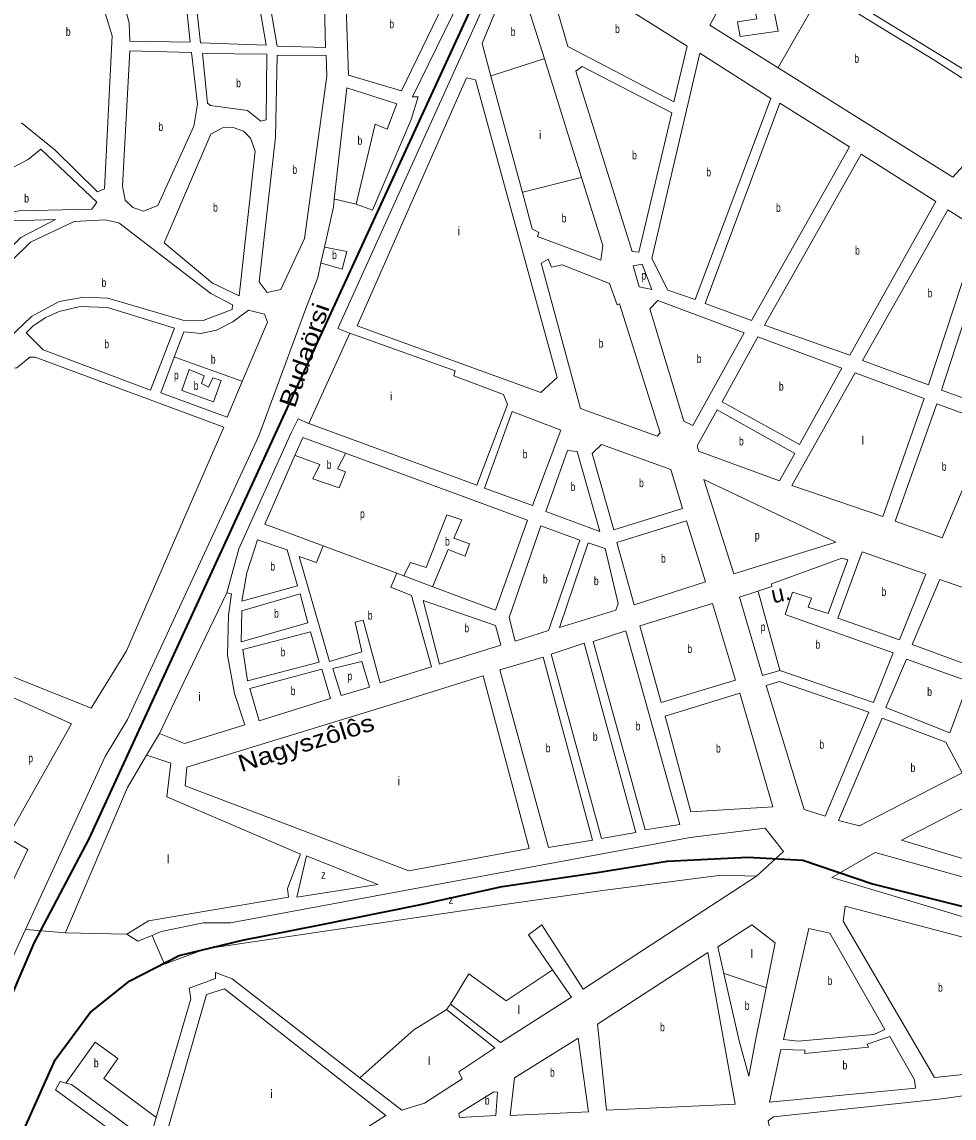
# Model space of a CAD drawing. Extents: x 639657 to 671642, y 222838 to 252123.
# Drawn here: x 648074 to 649169, y 236282 to 237569 of the extents above; entities that cross this region are included whole.
import ezdxf
from ezdxf.enums import TextEntityAlignment as Align

# ---------------------------------------------------------------- set-up
doc = ezdxf.new("R2010")
doc.units = 0
doc.header["$LTSCALE"] = 4
for name, color, linetype, lineweight in [('1', 7, 'Continuous', 13), ('21', 7, 'Continuous', 13), ('57', 7, 'Continuous', 35)]:
    doc.layers.add(name, color=color, linetype=linetype, lineweight=lineweight)
doc.layers.add('22', color=7, linetype='Continuous')
doc.layers.add('7', color=7, linetype='Continuous')

msp = doc.modelspace()

# ---------------------------------------------------------------- linework, layer by layer
at = {"layer": '1'}
for p, q in [((649167.54, 237387.09), (648962.215, 237515.472)), ((648485.97, 237348.354), (648466.758, 237355.344)), ((648264.4, 237205.4), (648253.167, 237175.527)), ((648359.66, 236979.18), (648394.815, 237060.136)), ((648428.159, 236953.689), (648359.66, 236979.18)), ((648937.039, 236565.79), (648733.55, 236432.94)), ((648733.55, 236432.94), (648684.736, 236508.716)), ((648935.92, 236372.66), (648948.453, 236434.804))]:
    msp.add_line(p, q, dxfattribs=at)
for points in [[(648254.02, 237981.68), (648247.99, 237983.13), (648181.41, 237912.62), (648180.29, 237896.05), (648248.49, 237711.3), (648266.09, 237648.23), (648277.25, 237605.11), (648283.86, 237544.73), (648361.03, 237542.22), (648330.04, 237723.02), (648273.61, 237889.81), (648264.29, 237942.2)], [(648109.77, 237833.46), (648158.88, 237887.89), (648171.57, 237886.07), (648239.72, 237707.77), (648266.1, 237602.64), (648271.82, 237545.48), (648200.89, 237546.76), (648200.25, 237568.48), (648173.08, 237666.3), (648172.5, 237681.13), (648107.94, 237822.47)], [(649014.45, 237615.58), (648948.94, 237656.48), (648951.26, 237661.02), (648939.15, 237669.29), (648980.29, 237746.67), (649048.84, 237703.64), (649137.09, 237644.67), (649176.39, 237625.03), (649293.79, 237530.85), (649238.75, 237467.54), (649191.95, 237506.25)], [(648430.69, 237539.21), (648373.94, 237541.05), (648357.75, 237636.39), (648416.42, 237657.36), (648429.03, 237620.49)], [(648453.41, 237633.19), (648457.87, 237506.77), (648519.94, 237488.42), (648581.24, 237614.8), (648557.49, 237626.19), (648523.01, 237635.34)], [(648839.83, 237475.46), (648715.2, 237540.34), (648690.28, 237627.42), (648703.08, 237637), (648855.52, 237540.77)], [(648192.24, 237376.57), (648201, 237535.58), (648273.44, 237533.46), (648280.48, 237472.66), (648276.01, 237447.03), (648233.72, 237353.73), (648217.24, 237347.12), (648204.52, 237351.31), (648195.63, 237359.83)], [(648292.08, 237473.84), (648286.35, 237532.29), (648362, 237531.48), (648361.03, 237454.48), (648354.82, 237452.92), (648339, 237465.46), (648295.76, 237471.08)], [(648432.52, 237505.68), (648431.64, 237529.76), (648374.04, 237530.3), (648372.19, 237434.15), (648353.01, 237263.86), (648362.37, 237251.47), (648378.24, 237254.84), (648406.02, 237314.89)], [(648870.43, 237532.52), (648813.91, 237291.35), (648832.75, 237254.32), (648864.87, 237243.43), (648953.9, 237479.32)], [(648798.79, 237298.74), (648790.83, 237299.52), (648724.93, 237511.61), (648732.19, 237516.84), (648837.59, 237462.54)], [(648702.88, 237151.82), (648683.5, 237134.01), (648467.84, 237212.45), (648596.29, 237503.54), (648607.06, 237501.27)], [(648876.53, 237238.38), (648931.09, 237218.67), (649046, 237422.53), (648964.27, 237473.82)], [(648348.28, 237417.58), (648329.53, 237247.73), (648298.23, 237262.28), (648241.25, 237309.71), (648296.08, 237437.53), (648309.98, 237444.76), (648322.44, 237445.3), (648334.52, 237441.11), (648342.55, 237432.8)], [(648036.14, 237341.36), (648020.91, 237334.13), (647956.16, 237294.38), (647947.36, 237300.59), (647944.97, 237309.18), (647952.04, 237320.37), (647969.9, 237343.02), (648024.18, 237377.81), (648081.48, 237407.59), (648096.62, 237419.99), (648162.34, 237357.8), (648156.41, 237349.36), (648070.9, 237347.27)], [(649046.46, 237177.8), (648946.4, 237213.22), (649060.05, 237413.84), (649147.41, 237358.52)], [(649061.35, 237171.48), (649138.77, 237142.95), (649198.67, 237325.01), (649161.48, 237348.54)], [(647978.05, 237242.85), (648008.9, 237203.08), (648017.07, 237204.62), (648052.92, 237295.92), (648073.14, 237316.11), (648113.76, 237337.35), (648063.71, 237335.59), (648028.35, 237324.94), (647999.79, 237310.36), (647962.25, 237285.99), (647960.34, 237278.26)], [(648027.41, 237201.92), (648028.42, 237185.59), (648036.22, 237179.21), (648048.39, 237188.14), (648085.65, 237223.32), (648117.93, 237240.82), (648147.1, 237246.04), (648175.05, 237245.01), (648263.41, 237218.94), (648287.05, 237218.73), (648321.31, 237231.52), (648321.68, 237237.12), (648295.98, 237250.21), (648188.15, 237333.3), (648172.21, 237337.03), (648135.49, 237334.75), (648084.15, 237310.62), (648061.8, 237288.48)], [(649154.3, 237136.86), (649385.27, 237053.18), (649450.68, 237199.6), (649265.5, 237280.69), (649219.43, 237311.23), (649214.73, 237308.6), (649210.42, 237309.86)], [(648823.64, 237086.48), (648776.17, 237238.09), (648773.39, 237236.99), (648764.34, 237262.07), (648708.89, 237283.92), (648696.02, 237281.44), (648692.28, 237290.65), (648683.95, 237286.06), (648730.1, 237115.3), (648820.46, 237082.8)], [(648792.064, 237282.711), (648802.618, 237284.823), (648814.228, 237254.955), (648799.301, 237258.274)], [(648862.03, 237095.23), (648922.42, 237204.18), (648821.26, 237242.17), (648811.69, 237232.19), (648851.45, 237100.29)], [(648079.39, 237204.12), (648099.35, 237184.31), (648225.32, 237136.87), (648253.4, 237209.39), (648174.73, 237233.82), (648142.7, 237235.03), (648118.04, 237229.21), (648102.21, 237221.97), (648087.48, 237212.15)], [(648608.49, 237025.14), (648644.52, 237120.1), (648639.9, 237131.67), (648581.66, 237153.5), (648582.89, 237159.53), (648459.54, 237203.55), (648411.37, 237097.51)], [(648987.31, 237072.73), (649037.37, 237162.44), (648938.58, 237199.59), (648896.57, 237122.86)], [(648978.33, 237024.69), (649085.49, 236988.47), (649133.99, 237126.99), (649052.68, 237156.99)], [(648981.83, 237062.35), (648963.88, 237030.14), (648868.98, 237065.18), (648867.42, 237071.19), (648890.64, 237113.56)], [(649211.64, 237097.6), (649148.88, 237120.68), (649099.94, 236982.8), (649154.93, 236963.31)], [(648617.33, 237021.78), (648650.19, 237111.76), (648707.14, 237089.71), (648674.05, 237001.44)], [(648726.3, 237064.72), (648752.79, 236970.77), (648689.38, 236994.27), (648714.89, 237065.91)], [(648769.53, 236972.65), (648850.09, 236997.69), (648836.53, 237043.38), (648755.01, 237072.95), (648744.15, 237062.52)], [(648910.33, 236920.811), (649030.2, 236957.987), (648875.091, 237031.614)], [(648729.68, 236960.66), (648683.53, 236977.44), (648646.54, 236869.79), (648653.48, 236841.89), (648692.68, 236854.51)], [(648876.93, 236911.49), (648854.95, 236983.33), (648772.9, 236957.84), (648793.17, 236884.69)], [(648397.76, 236907.06), (648332.61, 236888.82), (648338.3, 236922.21), (648351.03, 236960.82), (648385.96, 236949.1)], [(648759.43, 236950.83), (648739.16, 236957.53), (648705.75, 236857.86), (648771.74, 236878.26), (648774.46, 236886.24)], [(649060.96, 236946.95), (649032.5, 236869.05), (649104.96, 236843.27), (649136, 236920.77)], [(649192.3, 236811.17), (649221.62, 236889.94), (649152.18, 236914.46), (649119.62, 236837.81)], [(648410.01, 236863.3), (648331.57, 236841.28), (648332.72, 236877.64), (648400.86, 236897.62)], [(648636.76, 236837.22), (648630.52, 236860.39), (648545.56, 236889.71), (648564.56, 236815.05)], [(648912.44, 236796.11), (648824.81, 236769.71), (648799.86, 236860.02), (648885.13, 236885.97)], [(648423.35, 236817.18), (648339.11, 236795.33), (648333.59, 236832.05), (648413.33, 236852.79)], [(648806.07, 236620.28), (648745.24, 236841.45), (648783.59, 236853.85), (648846.84, 236626.68)], [(648755.02, 236610.13), (648695.75, 236826.58), (648734.52, 236839.42), (648795.36, 236616.96)], [(648439.524, 236809.779), (648473.56, 236818.103), (648482.427, 236787.792), (648449.175, 236778.181)], [(648692.81, 236599.45), (648635.54, 236808.39), (648686.54, 236823.27), (648744.3, 236608.1)], [(649113.13, 236820.77), (649088.76, 236763.76), (649164.04, 236734.35), (649186.45, 236794.34)], [(648436.66, 236774.51), (648352.9, 236748.14), (648341.99, 236786.11), (648426.66, 236808.82)], [(649068.82, 236758.42), (648964.03, 236794.65), (648948.18, 236789.78), (648992.8, 236643.95), (649017.58, 236636.22)], [(647984.42, 236666.97), (648050.57, 236781.68), (648132.45, 236744.6), (648062.74, 236620.94)], [(648860.02, 236641.43), (648829.69, 236753.84), (648917.32, 236780.67), (648956.02, 236647.26)], [(649033.32, 236631.2), (649084.58, 236751.25), (649159.21, 236723.12), (649178.47, 236687.39), (649058.09, 236624.98)], [(649107.25, 236608.23), (649251.37, 236682.68), (649266.1, 236560.45)], [(648408.59, 236589.672), (648397.311, 236541.151), (648492.414, 236555.876)], [(649145.87, 236329.44), (649187.52, 236333.48), (649226.9, 236481.59), (649041.18, 236530.63), (649038.56, 236512.75)], [(649087.73, 236385.68), (649074.89, 236379.96), (648985.78, 236372.04), (648968.58, 236373.82), (648998.25, 236504.21), (649023.01, 236498.84)], [(648879.68, 236476.01), (648750.28, 236391.8), (648760.94, 236291.04), (648911.72, 236298.02)], [(648238.56, 236243.84), (648331.62, 236176.53), (648501.84, 236284.56), (648312.35, 236433.56), (648291.14, 236426.91)], [(648647.75, 236284.83), (648652.9, 236328.96), (648727.66, 236375.68), (648739.47, 236288.9)], [(649123.64, 236316.76), (649122.69, 236326.43), (649093.4, 236377.34), (649067.05, 236368.28), (649068.37, 236364.85), (648993.66, 236357.28), (648993.62, 236361.58), (648965.47, 236362.18), (648952.1, 236300.12)], [(649211.77, 236051.33), (649200.52, 236190.58), (649195.28, 236199.35), (649206.93, 236216.23), (649295.793, 236324.572), (649154.49, 236304.35), (648956.78, 236283.17), (648950.81, 236278.38), (649005.5, 236003.83)], [(648630.99, 236284.67), (648632.66, 236312), (648628.35, 236312.61), (648587.34, 236287.07), (648588.25, 236282.34)]]:
    msp.add_lwpolyline(points, close=True, dxfattribs=at)
for points in [[(648003.985, 237761.114), (648010.17, 237755.54), (648061.18, 237682.04), (648081.36, 237661.79), (648105.57, 237647.18), (648136.37, 237639.93), (648159.34, 237620.79), (648180.42, 237553.03), (648171.43, 237373.15), (648163.08, 237369.85), (648113.39, 237418.64), (648073.97, 237450.75)], [(648635.931, 237692.189), (648533.101, 237481.453), (648539.735, 237481.453), (648531.442, 237454.904), (648485.97, 237348.354)], [(648652.517, 237667.299), (648445.197, 237209.322), (648459.04, 237203.751), (648459.54, 237203.55)], [(648962.215, 237515.472), (648882.14, 237565.54), (648930.9, 237655.67), (649013.526, 237605.308)], [(648624.978, 237505.815), (648614.59, 237544.14), (648646.29, 237620.56), (648658.77, 237618.96), (648687.863, 237526.037), (648731.544, 237386.519)], [(649013.526, 237605.308), (649145.35, 237524.96), (649197.26, 237491.03), (649233.24, 237459.1), (649167.54, 237387.09)], [(648673.67, 237326.18), (648662.028, 237369.131), (648624.978, 237505.815)], [(648441.134, 237361.26), (648455.86, 237491.91), (648514.717, 237473.117)], [(648514.717, 237473.117), (648503.247, 237443.289), (648489.15, 237449.097), (648466.758, 237355.344)], [(648731.544, 237386.519), (648756.59, 237306.52), (648753.97, 237289.5), (648679.77, 237317.42), (648681.23, 237322.16), (648673.67, 237326.18)], [(648429.601, 237304.644), (648440.04, 237351.55), (648441.134, 237361.26)], [(648407.68, 237232.75), (648421.72, 237269.23), (648425.5, 237286.215), (648429.601, 237304.644)], [(648407.68, 237232.75), (648352.317, 237083.212), (648198.071, 236749.685), (648171.93, 236706.47)], [(648333.109, 237147.029), (648362.71, 237216.64), (648358.97, 237225.85), (648340.44, 237230.84), (648321.88, 237217.12), (648302.64, 237207.05), (648284.41, 237203.22), (648264.4, 237205.4)], [(647887.225, 237144.175), (647891.754, 237141.496), (647972.84, 237093.53), (647981.22, 237091.19), (647995.9, 237093.86), (648035.57, 237158.12), (648045.83, 237163.38), (648057.02, 237162.19), (648068.19, 237163.16), (648083.75, 237175.34), (648089.77, 237175.4), (648311.48, 237093.36), (648197.15, 236830.36), (648155.48, 236763.09), (648040.74, 236809.02)], [(648253.167, 237175.527), (648237.38, 237133.54), (648315.24, 237105.01), (648333.109, 237147.029)], [(648314.89, 236898.76), (648329.098, 236950.465), (648390.464, 237086.531), (648398.757, 237103.124), (648410.87, 237097.733), (648411.37, 237097.51)], [(648394.815, 237060.136), (648404.01, 237081.31), (648454.443, 237062.768)], [(648454.443, 237062.768), (648668.2, 236984.18), (648630.34, 236878.45), (648556.784, 236905.822), (648522.641, 236918.528), (648514.394, 236921.597)], [(648428.159, 236953.689), (648420.356, 236934.171), (648399.79, 236941.27), (648435.37, 236818.15), (648473.3, 236829.26), (648465.66, 236864.03), (648474.87, 236866.69), (648495.15, 236793.11), (648555.35, 236811.74)], [(648964.533, 236807.337), (649074.3, 236769.65), (649097.37, 236828.36), (648970.57, 236873.21), (648979.12, 236899.31), (649001.54, 236892.21), (648997.56, 236881.85), (649021.27, 236874.54), (649044.29, 236937.55), (649037.18, 236939.42), (648954.53, 236909.41)], [(648555.35, 236811.74), (648531.75, 236895.61), (648507.551, 236905.338), (648514.394, 236921.597)], [(648954.53, 236909.41), (648954.99, 236905.97), (648938.586, 236900.555)], [(648314.89, 236898.76), (648320.49, 236897.52), (648316.87, 236872.33), (648315.61, 236825.43), (648324, 236780.35), (648335.96, 236743.68), (648265.05, 236721.74), (648235.71, 236733.51)], [(648938.586, 236900.555), (648916.982, 236893.423), (648944.154, 236801.674), (648964.533, 236807.337)], [(648518.57, 236770.53), (648616.05, 236801.11), (648670.04, 236598.16), (648570.94, 236580.04)], [(648265.96, 236672.06), (648268.11, 236693.81), (648518.57, 236770.53)], [(647872.536, 236168.951), (648000.85, 236383.75), (648056.41, 236455.5), (648078.362, 236503.191), (648171.93, 236706.47)], [(648220.619, 236708.06), (648221.119, 236707.893), (648248.996, 236698.597), (648244.467, 236658.952), (648401.49, 236591.6), (648385.98, 236551.45), (648387.15, 236541.14), (648223.03, 236513.17), (648197.61, 236497.66)], [(648570.94, 236580.04), (648528.47, 236571.91), (648265.96, 236672.06)], [(648060.306, 236553.799), (648081.03, 236597.02), (648037.15, 236623.07), (648016.29, 236580.08), (648009.14, 236586.89)], [(648227.067, 236496.276), (648237.98, 236500.83), (648287.52, 236510.97), (648319.11, 236510.83), (648859.02, 236611.1), (648947.02, 236622.02), (648968.78, 236594.91), (648937.039, 236565.79)], [(649076.172, 236593.467), (649025.49, 236564.273), (649393.627, 236453.931)], [(649405.677, 236499.881), (649269.685, 236539.688), (649076.172, 236593.467)], [(648684.736, 236508.716), (648669.371, 236496.734), (648697.553, 236455.736)], [(648948.453, 236434.804), (648959.08, 236487.5), (648931.59, 236508.54), (648891.44, 236482.79), (648898.586, 236451.434)], [(648197.61, 236497.66), (648210.59, 236489.4), (648227.067, 236496.276)], [(648471.177, 236328.982), (648321.26, 236445.26), (648301.63, 236452.6), (648301.7, 236445.72), (648270.65, 236434.25), (648272.71, 236421.58), (648231.905, 236282.345)], [(648697.553, 236455.736), (648719.67, 236423.56), (648636.17, 236370.32), (648577.7, 236415.58), (648573.04, 236409.09)], [(648898.586, 236451.434), (648916.58, 236372.48), (648927.822, 236330.656), (648935.92, 236372.66)], [(648573.04, 236409.09), (648629.78, 236364.02), (648587.29, 236335.88), (648591.46, 236327.54), (648547.25, 236299.17), (648520.47, 236290.75), (648471.177, 236328.982)], [(648125.935, 236322.695), (648119.36, 236324.46), (648113.87, 236314.73), (648219.07, 236237.64), (648171.68, 236073.32), (648139.86, 236052.6), (648140.01, 236037.11), (648097.67, 236007.21), (648072.36, 235735.76), (648060.22, 235639.98), (648068.62, 235637.88), (648076.25, 235693.63), (648105.08, 235690.13), (648075.64, 235537.49), (648070.11, 235527.13), (648098.499, 235356.253)], [(648231.905, 236282.345), (648225.5, 236260.49), (648217.57, 236258.48), (648132.51, 236320.93), (648125.935, 236322.695)]]:
    msp.add_lwpolyline(points, dxfattribs=at)
at = {"layer": '21'}
msp.add_line((648514.394, 236921.597), (648428.159, 236953.689), dxfattribs=at)
for points in [[(648917.866, 237552.321), (648962.268, 237558.324), (648952.078, 237608.163), (648969.061, 237611.561), (648965.664, 237627.419), (648928.303, 237619.49), (648937.36, 237573.049), (648914.716, 237569.651)], [(648270.811, 237161.004), (648261.926, 237136.31), (648299.244, 237123.035), (648308.366, 237147.925), (648298.414, 237151.244), (648293.439, 237140.458), (648285.146, 237144.606), (648288.463, 237153.733)]]:
    msp.add_lwpolyline(points, close=True, dxfattribs=at)
for points in [[(648962.215, 237515.472), (648962.501, 237515.972), (649013.24, 237604.808), (649013.526, 237605.308)], [(648624.978, 237505.815), (648625.478, 237505.976), (648687.363, 237525.876), (648687.863, 237526.037)], [(648662.028, 237369.131), (648662.528, 237369.256), (648731.044, 237386.394), (648731.544, 237386.519)], [(648466.758, 237355.344), (648441.634, 237361.145), (648441.134, 237361.26)], [(648429.601, 237304.644), (648430.101, 237304.551), (648455.979, 237299.757), (648450.174, 237279.015), (648426, 237286.069), (648425.5, 237286.215)], [(648253.167, 237175.527), (648253.667, 237175.349), (648332.609, 237147.207), (648333.109, 237147.029)], [(648394.815, 237060.136), (648395.315, 237059.954), (648424.051, 237049.499), (648415.922, 237032.496), (648446.958, 237022.146), (648454.347, 237040.628), (648444.741, 237044.324), (648454.18, 237062.268), (648454.443, 237062.768)], [(648556.784, 236905.822), (648556.989, 236906.323), (648574.795, 236949.696), (648594.746, 236941.564), (648599.919, 236956.349), (648581.445, 236963.003), (648591.051, 236984.442), (648573.317, 236990.356), (648548.932, 236928.256), (648530.458, 236934.171), (648522.891, 236919.029), (648522.641, 236918.528)], [(648314.89, 236898.76), (648264.414, 236793.658), (648235.71, 236733.51)], [(648964.533, 236807.337), (648964.394, 236807.837), (648938.725, 236900.055), (648938.586, 236900.555)], [(648198.071, 236670.037), (648220.619, 236708.06), (648235.71, 236733.51)], [(648198.071, 236670.037), (648125.308, 236499.625), (648125.095, 236499.125)], [(648937.039, 236565.79), (648895.56, 236566.92), (648753.26, 236548.39), (648638.24, 236532.28)], [(648227.067, 236496.276), (648229.209, 236491.276), (648241.533, 236462.506), (648290.303, 236480.249), (648638.24, 236532.28)], [(648125.095, 236499.125), (648078.862, 236503.147), (648078.362, 236503.191)], [(648197.61, 236497.66), (648197.11, 236497.67), (648125.095, 236499.125)], [(648697.553, 236455.736), (648697.053, 236455.403), (648643.082, 236419.405), (648599.276, 236451.18), (648578.003, 236416.08), (648577.7, 236415.58)], [(648948.453, 236434.804), (648947.953, 236434.971), (648899.086, 236451.267), (648898.586, 236451.434)], [(648573.04, 236409.09), (648572.54, 236408.782), (648534.662, 236385.44), (648471.677, 236329.427), (648471.177, 236328.982)], [(648125.935, 236322.695), (648126.291, 236323.195), (648160.25, 236370.834), (648186.852, 236351.613), (648170.595, 236327.956), (648231.405, 236282.717), (648231.905, 236282.345)]]:
    msp.add_lwpolyline(points, dxfattribs=at)
at = {"layer": '57'}
for points in [[(648764.444, 238156.794), (648760.356, 238056.15), (648755.321, 237936.134), (648642.478, 237674.613), (648152.957, 236609.517), (648088.384, 236487.179), (648047.188, 236392.076), (648029.423, 236322.423), (648014.054, 235904.557)], [(648056.694, 236178.651), (648077.383, 236269.56), (648113.411, 236350.225), (648154.274, 236405.789), (648201.05, 236442.66), (648258.986, 236472.731), (648333.334, 236490.803), (648424.501, 236508.623), (648540.719, 236532.049), (648638.396, 236553.637), (648749.723, 236570.284), (648832.114, 236583.501), (648926.736, 236588.164), (648991.288, 236584.772), (649073.136, 236556.912), (649237.676, 236515.501)]]:
    msp.add_lwpolyline(points, dxfattribs=at)

# ---------------------------------------------------------------- texts
at = {"layer": '22', "width": 1.2}
for s, rotation, p in [('Budaörsi', 71.005, (648415.346, 237174.561)), ('Nagyszôlôs', 17.55, (648410.957, 236712.908))]:
    msp.add_text(s, height=20, rotation=rotation, dxfattribs=at).set_placement(p, align=Align.CENTER)
at = {"layer": '22'}
msp.add_text('u.  ', height=20, rotation=12.4, dxfattribs=at).set_placement((648974.608, 236890.184), align=Align.CENTER)
at = {"layer": '7'}
for s, width, p in [('b', 0.75, (648125.881, 237552.987)), ('b', 0.75, (648505.749, 237561.88)), ('b', 0.75, (648770.841, 237556.23)), ('b', 0.75, (648648.371, 237552.806)), ('b', 0.75, (649051.797, 237521.38)), ('b', 0.75, (648325.875, 237492.605)), ('b', 0.75, (648234.622, 237441.35)), ('b', 0.75, (648468.418, 237425.036)), ('b', 0.75, (648790.905, 237407.79)), ('b', 0.75, (648391.946, 237390.885)), ('b', 0.75, (648877.99, 237387.975)), ('b', 0.75, (648076.954, 237357.185)), ('b', 0.75, (648298.736, 237346.515)), ('b', 0.75, (648959.864, 237346.245)), ('b', 0.75, (648708.08, 237333.773)), ('b', 0.75, (649052.789, 237295.82)), ('b', 0.75, (648438.564, 237290.631)), ('b', 0.75, (648167.726, 237258.12)), ('p', 0.75, (648801.789, 237266.57)), ('b', 0.75, (649137.969, 237245.745)), ('b', 0.75, (648171.011, 237185.95)), ('b', 0.75, (648751.525, 237186.725)), ('b', 0.75, (648296.152, 237167.925)), ('b', 0.75, (648866.791, 237168.7)), ('p', 0.75, (648252.804, 237149.584)), ('b', 0.75, (648276.024, 237137.139)), ('b', 0.75, (648963.279, 237136.16)), ('b', 0.75, (648916.347, 237071.85)), ('b', 0.75, (648662.387, 237056.6)), ('b', 0.75, (648432.179, 237044.324)), ('b', 0.75, (649154.555, 237041.995)), ('b', 0.75, (648718.664, 237018.34)), ('b', 0.75, (648799.003, 237022.8)), ('p', 0.75, (648471.343, 236986.66)), ('b', 0.75, (648571.1, 236954.131)), ('p', 0.75, (648935.097, 236961.386)), ('b', 0.75, (648365.968, 236924.82)), ('b', 0.75, (648824.772, 236934.01)), ('b', 0.75, (648686.073, 236909.665)), ('b', 0.75, (648745.961, 236907.695)), ('b', 0.75, (649083.872, 236895.11)), ('b', 0.75, (648370.416, 236869.45)), ('b', 0.75, (648480.473, 236867.19)), ('b', 0.75, (648593.869, 236852.38)), ('p', 0.75, (648941.89, 236853.778)), ('b', 0.75, (649006.192, 236833.014)), ('b', 0.75, (648378.103, 236824.06)), ('b', 0.75, (648855.774, 236827.84)), ('p', 0.75, (648456.564, 236795.924)), ('b', 0.75, (648389.843, 236778.48)), ('b', 0.75, (649137.42, 236777.56)), ('b', 0.75, (648795.028, 236737.065)), ('b', 0.75, (648744.75, 236724.775)), ('b', 0.75, (648689.358, 236711.36)), ('b', 0.75, (648889.376, 236711.05)), ('b', 0.75, (649010.862, 236715.435)), ('p', 0.75, (648081.734, 236699.491)), ('b', 0.75, (649117.851, 236688.115)), ('z', 0.8, (648425.616, 236562.672)), ('z', 0.8, (648575.534, 236533.477)), ('b', 0.75, (649020.474, 236438.125)), ('b', 0.75, (649150.087, 236430.035)), ('b', 0.75, (648923.149, 236408.736)), ('b', 0.75, (648823.742, 236383.525)), ('b', 0.75, (648158.772, 236341.263)), ('b', 0.75, (648694.407, 236330.255)), ('b', 0.75, (649038.016, 236338.73)), ('b', 0.75, (648617.91, 236297.475))]:
    msp.add_text(s, height=10, dxfattribs=dict(at, width=width)).set_placement(p)
for s, p in [('i', (648681.543, 237431.674)), ('i', (648585.929, 237318.775)), ('i', (648506.318, 237124.632)), ('l', (649060.16, 237072.73)), ('i', (648281.39, 236771.708)), ('i', (648515.488, 236672.698)), ('l', (648244.467, 236580.796)), ('l', (648930.012, 236469.806)), ('l', (648656.224, 236404.066)), ('l', (648551.089, 236343.804)), ('i', (648365.964, 236305.045))]:
    msp.add_text(s, height=10, dxfattribs=at).set_placement(p)

doc.saveas('drawing.dxf')
